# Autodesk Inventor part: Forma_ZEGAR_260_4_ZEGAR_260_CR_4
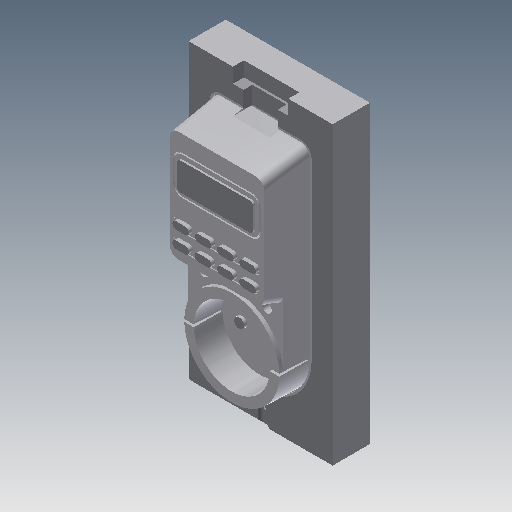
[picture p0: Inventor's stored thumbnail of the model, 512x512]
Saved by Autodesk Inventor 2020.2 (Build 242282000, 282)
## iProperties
Created: 2015-01
Part Number: Forma_ZEGAR_260_4_ZEGAR_260_CR_4
Material: Ogólny
Document SubType Name: Modeling
Designer: F.Stasiak
Density: 1 g/cm^3
Appearance: Domyślna
Catalog Web Link: www.expertbooks.pl
Manager: www.cadconsulting.pl
Company: Fabian Stasiak CAD Consulting
Author: F.Stasiak
Subject: Zbiór ćwiczeń. Autodesk Inventor 2020. Kurs Professional
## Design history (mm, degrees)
node "Forma_ZEGAR_260_4_ZEGAR_260_CR_Base"
feature "Rzeźbienie3"
feature "Bryła1::Forma_ZEGAR_260_4_ZEGAR_260_CR_Base"
tag "Bryła wyprowadzona1"
node "Bryła1"
feature "Forma_ZEGAR_260_4_ZEGAR_260_CR_Base_Bodies"
feature "Powierzchnia3"
body "Srf3"
